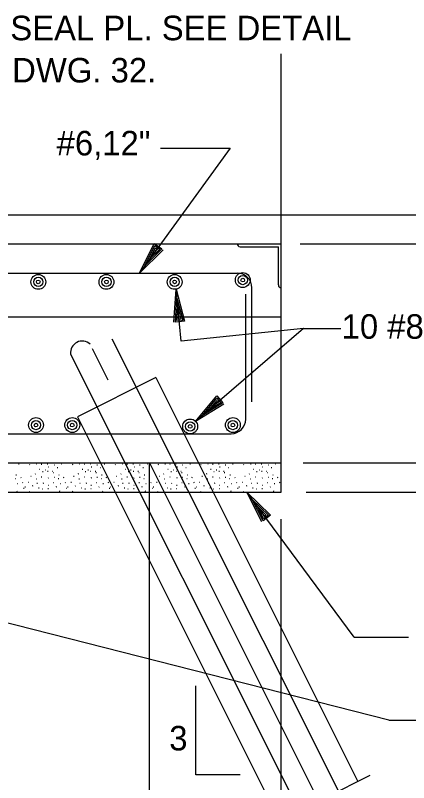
# Model space of a CAD drawing. Extents: x 6 to 106, y 3 to 74.
# Drawn here: x 90.92 to 96.9, y 51.44 to 63.12 of the extents above; entities that cross this region are included whole.
import ezdxf

# ---------------------------------------------------------------- set-up
doc = ezdxf.new("R2010")
doc.units = 0
for name, color, linetype in [('Level 22', 7, 'Continuous'), ('Level 44', 7, 'Continuous'), ('Level 50', 7, 'Continuous')]:
    doc.layers.add(name, color=color, linetype=linetype)

msp = doc.modelspace()

# ---------------------------------------------------------------- linework, layer by layer
at = {"layer": 'Level 22'}
for p, q in [((94.962, 55.863), (94.962, 62.532)), ((94.188, 61.099), (92.808, 59.196)), ((93.129, 61.099), (94.188, 61.099)), ((87.475, 60.085), (98.111, 60.085)), ((89.233, 59.641), (94.962, 59.641)), ((94.337, 59.599), (94.92, 59.599)), ((94.92, 59.016), (94.92, 59.599)), ((95.251, 59.641), (99.7, 59.641)), ((89.722, 59.196), (94.295, 59.196)), ((93.442, 58.16), (93.365, 58.952)), ((94.424, 56.974), (94.424, 58.877)), ((94.517, 57.238), (94.517, 58.974)), ((84.295, 58.53), (94.962, 58.53)), ((95.303, 58.356), (93.442, 58.16)), ((95.303, 58.356), (93.662, 56.94)), ((95.303, 58.356), (95.872, 58.356)), ((92.389, 58.198), (95.832, 51.312)), ((92.091, 58.049), (92.329, 57.572)), ((91.76, 57.965), (95.236, 51.014)), ((93.058, 57.606), (91.865, 57.009)), ((93.058, 57.606), (96.13, 51.461)), ((91.865, 57.009), (94.938, 50.865)), ((84.869, 56.752), (94.202, 56.752)), ((84.295, 56.307), (94.962, 56.307)), ((92.962, 56.307), (96.684, 48.864)), ((92.962, 49.491), (92.962, 56.307)), ((95.297, 56.307), (99.643, 56.307)), ((84.295, 55.863), (94.962, 55.863)), ((96.074, 53.656), (94.439, 55.863)), ((95.342, 55.863), (98.283, 55.863)), ((94.962, 47.814), (94.962, 55.451)), ((96.599, 52.392), (90.406, 53.969)), ((96.074, 53.656), (96.899, 53.656)), ((93.665, 51.56), (93.665, 52.916)), ((96.599, 52.392), (98.151, 52.392)), ((94.337, 51.56), (93.665, 51.56)), ((95.651, 51.221), (96.316, 51.554))]:
    msp.add_line(p, q, dxfattribs=at)
for centre, radius, start, end in [((94.337, 59.641), 0.0417, 180, 270), ((94.295, 58.974), 0.222, 0, 90), ((94.962, 59.016), 0.0417, 180, 270), ((91.937, 57.984), 0.178, 47.1608, 185.9736), ((94.202, 56.974), 0.222, 270, 0)]:
    msp.add_arc(centre, radius, start, end, dxfattribs=at)
at = {"layer": 'Level 44'}
for p, q in [((90.979, 56.29), (90.971, 56.29)), ((91.25, 56.29), (91.243, 56.29)), ((91.629, 56.29), (91.622, 56.29)), ((91.901, 56.29), (91.894, 56.29)), ((92.28, 56.29), (92.273, 56.29)), ((92.552, 56.29), (92.545, 56.29)), ((92.931, 56.29), (92.924, 56.29)), ((93.203, 56.29), (93.195, 56.29)), ((93.582, 56.29), (93.575, 56.29)), ((93.854, 56.29), (93.846, 56.29)), ((94.233, 56.29), (94.225, 56.29)), ((94.504, 56.29), (94.497, 56.29)), ((94.884, 56.29), (94.876, 56.29)), ((91.143, 56.284), (91.135, 56.28)), ((91.294, 56.207), (91.287, 56.206)), ((91.324, 56.285), (91.316, 56.285)), ((91.343, 56.173), (91.334, 56.173)), ((91.38, 56.197), (91.373, 56.197)), ((91.414, 56.288), (91.407, 56.287)), ((91.419, 56.177), (91.412, 56.176)), ((91.431, 56.241), (91.424, 56.241)), ((91.492, 56.177), (91.484, 56.177)), ((91.517, 56.275), (91.51, 56.275)), ((91.566, 56.234), (91.559, 56.233)), ((91.794, 56.284), (91.786, 56.28)), ((91.945, 56.207), (91.938, 56.206)), ((91.975, 56.285), (91.967, 56.285)), ((91.994, 56.173), (91.985, 56.173)), ((92.031, 56.197), (92.024, 56.197)), ((92.065, 56.288), (92.058, 56.287)), ((92.07, 56.177), (92.063, 56.176)), ((92.082, 56.241), (92.075, 56.241)), ((92.143, 56.177), (92.134, 56.177)), ((92.168, 56.275), (92.16, 56.275)), ((92.217, 56.234), (92.209, 56.233)), ((92.445, 56.284), (92.437, 56.28)), ((92.596, 56.207), (92.589, 56.206)), ((92.625, 56.285), (92.618, 56.285)), ((92.644, 56.173), (92.635, 56.173)), ((92.682, 56.197), (92.674, 56.197)), ((92.716, 56.288), (92.709, 56.287)), ((92.721, 56.177), (92.713, 56.176)), ((92.733, 56.241), (92.726, 56.241)), ((92.794, 56.177), (92.785, 56.177)), ((92.819, 56.275), (92.811, 56.275)), ((92.868, 56.234), (92.86, 56.233)), ((93.096, 56.284), (93.088, 56.28)), ((93.247, 56.207), (93.24, 56.206)), ((93.276, 56.285), (93.269, 56.285)), ((93.295, 56.173), (93.286, 56.173)), ((93.333, 56.197), (93.325, 56.197)), ((93.367, 56.288), (93.359, 56.287)), ((93.372, 56.177), (93.364, 56.176)), ((93.384, 56.241), (93.376, 56.241)), ((93.444, 56.177), (93.436, 56.177)), ((93.469, 56.275), (93.462, 56.275)), ((93.518, 56.234), (93.511, 56.233)), ((93.747, 56.284), (93.739, 56.28)), ((93.898, 56.207), (93.89, 56.206)), ((93.927, 56.285), (93.92, 56.285)), ((93.946, 56.173), (93.937, 56.173)), ((93.983, 56.197), (93.976, 56.197)), ((94.018, 56.288), (94.01, 56.287)), ((94.023, 56.177), (94.015, 56.176)), ((94.035, 56.241), (94.027, 56.241)), ((94.095, 56.177), (94.087, 56.177)), ((94.12, 56.275), (94.113, 56.275)), ((94.169, 56.234), (94.162, 56.233)), ((94.397, 56.284), (94.39, 56.28)), ((94.549, 56.207), (94.541, 56.206)), ((94.578, 56.285), (94.571, 56.285)), ((94.597, 56.173), (94.588, 56.173)), ((94.634, 56.197), (94.627, 56.197)), ((94.668, 56.288), (94.661, 56.287)), ((94.673, 56.177), (94.666, 56.176)), ((94.685, 56.241), (94.678, 56.241)), ((94.746, 56.177), (94.738, 56.177)), ((94.771, 56.275), (94.764, 56.275)), ((94.82, 56.234), (94.813, 56.233)), ((90.93, 56.064), (90.922, 56.064)), ((90.937, 56.12), (90.93, 56.12)), ((91.011, 56.083), (91.002, 56.084)), ((91.162, 56.101), (91.155, 56.1)), ((91.228, 56.14), (91.221, 56.139)), ((91.243, 56.062), (91.236, 56.061)), ((91.324, 56.091), (91.316, 56.091)), ((91.427, 56.079), (91.419, 56.078)), ((91.502, 56.157), (91.495, 56.157)), ((91.517, 56.086), (91.51, 56.086)), ((91.581, 56.064), (91.573, 56.064)), ((91.588, 56.12), (91.581, 56.12)), ((91.662, 56.083), (91.653, 56.084)), ((91.813, 56.101), (91.806, 56.1)), ((91.879, 56.14), (91.872, 56.139)), ((91.894, 56.062), (91.886, 56.061)), ((91.975, 56.091), (91.967, 56.091)), ((92.077, 56.079), (92.07, 56.078)), ((92.153, 56.157), (92.146, 56.157)), ((92.168, 56.086), (92.16, 56.086)), ((92.231, 56.064), (92.224, 56.064)), ((92.239, 56.12), (92.231, 56.12)), ((92.313, 56.083), (92.304, 56.084)), ((92.464, 56.101), (92.457, 56.1)), ((92.53, 56.14), (92.523, 56.139)), ((92.545, 56.062), (92.537, 56.061)), ((92.625, 56.091), (92.618, 56.091)), ((92.728, 56.079), (92.721, 56.078)), ((92.804, 56.157), (92.797, 56.157)), ((92.819, 56.086), (92.811, 56.086)), ((92.882, 56.064), (92.875, 56.064)), ((92.89, 56.12), (92.882, 56.12)), ((92.963, 56.083), (92.955, 56.084)), ((93.115, 56.101), (93.107, 56.1)), ((93.181, 56.14), (93.174, 56.139)), ((93.195, 56.062), (93.188, 56.061)), ((93.276, 56.091), (93.269, 56.091)), ((93.379, 56.079), (93.372, 56.078)), ((93.455, 56.157), (93.447, 56.157)), ((93.469, 56.086), (93.462, 56.086)), ((93.533, 56.064), (93.526, 56.064)), ((93.54, 56.12), (93.533, 56.12)), ((93.614, 56.083), (93.606, 56.084)), ((93.766, 56.101), (93.758, 56.1)), ((93.832, 56.14), (93.824, 56.139)), ((93.846, 56.062), (93.839, 56.061)), ((93.927, 56.091), (93.92, 56.091)), ((94.03, 56.079), (94.023, 56.078)), ((94.106, 56.157), (94.098, 56.157)), ((94.12, 56.086), (94.113, 56.086)), ((94.184, 56.064), (94.177, 56.064)), ((94.191, 56.12), (94.184, 56.12)), ((94.265, 56.083), (94.256, 56.084)), ((94.416, 56.101), (94.409, 56.1)), ((94.483, 56.14), (94.475, 56.139)), ((94.497, 56.062), (94.49, 56.061)), ((94.578, 56.091), (94.571, 56.091)), ((94.681, 56.079), (94.673, 56.078)), ((94.756, 56.157), (94.749, 56.157)), ((94.771, 56.086), (94.764, 56.086)), ((94.835, 56.064), (94.827, 56.064)), ((94.842, 56.12), (94.835, 56.12)), ((94.916, 56.083), (94.907, 56.084)), ((90.959, 55.991), (90.952, 55.99)), ((91.035, 56.008), (91.028, 56.007)), ((91.073, 55.937), (91.066, 55.941)), ((91.123, 56.01), (91.116, 56.01)), ((91.187, 55.957), (91.179, 55.956)), ((91.258, 55.996), (91.25, 55.995)), ((91.35, 55.998), (91.341, 55.996)), ((91.427, 55.966), (91.419, 55.966)), ((91.505, 56.007), (91.499, 56.005)), ((91.546, 55.942), (91.539, 55.941)), ((91.61, 55.991), (91.603, 55.99)), ((91.686, 56.008), (91.678, 56.007)), ((91.724, 55.937), (91.716, 55.941)), ((91.774, 56.01), (91.767, 56.01)), ((91.838, 55.957), (91.83, 55.956)), ((91.908, 55.996), (91.901, 55.995)), ((92.001, 55.998), (91.992, 55.996)), ((92.077, 55.966), (92.07, 55.966)), ((92.156, 56.007), (92.15, 56.005)), ((92.197, 55.942), (92.19, 55.941)), ((92.261, 55.991), (92.253, 55.99)), ((92.337, 56.008), (92.329, 56.007)), ((92.375, 55.937), (92.367, 55.941)), ((92.425, 56.01), (92.417, 56.01)), ((92.488, 55.957), (92.481, 55.956)), ((92.559, 55.996), (92.552, 55.995)), ((92.652, 55.998), (92.643, 55.996)), ((92.728, 55.966), (92.721, 55.966)), ((92.807, 56.007), (92.8, 56.005)), ((92.848, 55.942), (92.841, 55.941)), ((92.912, 55.991), (92.904, 55.99)), ((92.987, 56.008), (92.98, 56.007)), ((93.026, 55.937), (93.018, 55.941)), ((93.076, 56.01), (93.068, 56.01)), ((93.139, 55.957), (93.132, 55.956)), ((93.21, 55.996), (93.203, 55.995)), ((93.302, 55.998), (93.293, 55.996)), ((93.379, 55.966), (93.372, 55.966)), ((93.458, 56.007), (93.451, 56.005)), ((93.499, 55.942), (93.492, 55.941)), ((93.562, 55.991), (93.555, 55.99)), ((93.638, 56.008), (93.631, 56.007)), ((93.676, 55.937), (93.669, 55.941)), ((93.726, 56.01), (93.719, 56.01)), ((93.79, 55.957), (93.783, 55.956)), ((93.861, 55.996), (93.854, 55.995)), ((93.953, 55.998), (93.944, 55.996)), ((94.03, 55.966), (94.023, 55.966)), ((94.108, 56.007), (94.102, 56.005)), ((94.15, 55.942), (94.142, 55.941)), ((94.213, 55.991), (94.206, 55.99)), ((94.289, 56.008), (94.282, 56.007)), ((94.327, 55.937), (94.32, 55.941)), ((94.377, 56.01), (94.37, 56.01)), ((94.441, 55.957), (94.433, 55.956)), ((94.512, 55.996), (94.504, 55.995)), ((94.604, 55.998), (94.595, 55.996)), ((94.681, 55.966), (94.673, 55.966)), ((94.759, 56.007), (94.753, 56.005)), ((94.801, 55.942), (94.793, 55.941)), ((94.864, 55.991), (94.857, 55.99)), ((94.94, 56.008), (94.933, 56.007)), ((90.95, 55.875), (90.943, 55.878)), ((91.055, 55.92), (91.047, 55.919)), ((91.143, 55.871), (91.135, 55.87)), ((91.282, 55.922), (91.275, 55.922)), ((91.336, 55.908), (91.329, 55.907)), ((91.424, 55.915), (91.417, 55.914)), ((91.601, 55.875), (91.594, 55.878)), ((91.705, 55.92), (91.698, 55.919)), ((91.794, 55.871), (91.786, 55.87)), ((91.933, 55.922), (91.926, 55.922)), ((91.987, 55.908), (91.979, 55.907)), ((92.075, 55.915), (92.067, 55.914)), ((92.252, 55.875), (92.245, 55.878)), ((92.356, 55.92), (92.349, 55.919)), ((92.444, 55.871), (92.437, 55.87)), ((92.584, 55.922), (92.576, 55.922)), ((92.638, 55.908), (92.63, 55.907)), ((92.726, 55.915), (92.718, 55.914)), ((92.903, 55.875), (92.896, 55.878)), ((93.007, 55.92), (93, 55.919)), ((93.095, 55.871), (93.088, 55.87)), ((93.235, 55.922), (93.227, 55.922)), ((93.288, 55.908), (93.281, 55.907)), ((93.376, 55.915), (93.369, 55.914)), ((93.554, 55.875), (93.547, 55.878)), ((93.658, 55.92), (93.651, 55.919)), ((93.746, 55.871), (93.739, 55.87)), ((93.885, 55.922), (93.878, 55.922)), ((93.939, 55.908), (93.932, 55.907)), ((94.027, 55.915), (94.02, 55.914)), ((94.205, 55.875), (94.198, 55.878)), ((94.309, 55.92), (94.301, 55.919)), ((94.397, 55.871), (94.39, 55.87)), ((94.536, 55.922), (94.529, 55.922)), ((94.59, 55.908), (94.583, 55.907)), ((94.678, 55.915), (94.671, 55.914)), ((94.855, 55.875), (94.848, 55.878)), ((94.96, 55.92), (94.952, 55.919))]:
    msp.add_line(p, q, dxfattribs=at)
at = {"layer": 'Level 50'}
for p, q in [((92.89, 59.309), (92.89, 59.309)), ((92.808, 59.196), (92.808, 59.196)), ((93.365, 58.952), (93.365, 58.952)), ((93.378, 58.814), (93.378, 58.814)), ((93.767, 57.031), (93.767, 57.031)), ((93.662, 56.94), (93.662, 56.94)), ((94.439, 55.863), (94.439, 55.863)), ((94.522, 55.752), (94.522, 55.752))]:
    msp.add_line(p, q, dxfattribs=at)
for points in [[(93.168, 59.551), (92.808, 59.196), (93.034, 59.649), (93.148, 59.566), (92.89, 59.309), (93.043, 59.616), (93.117, 59.562), (92.968, 59.416), (93.052, 59.583), (93.082, 59.561), (93.049, 59.529)], [(93.331, 58.448), (93.365, 58.952), (93.495, 58.464), (93.355, 58.45), (93.378, 58.814), (93.467, 58.483), (93.376, 58.474), (93.391, 58.682), (93.438, 58.501), (93.401, 58.498), (93.405, 58.544)], [(94.093, 57.203), (93.662, 56.94), (93.985, 57.328), (94.077, 57.221), (93.767, 57.031), (93.986, 57.294), (94.046, 57.225), (93.867, 57.118), (93.988, 57.26), (94.012, 57.232), (93.973, 57.208)], [(94.669, 55.413), (94.439, 55.863), (94.802, 55.512), (94.689, 55.427), (94.522, 55.752), (94.768, 55.513), (94.695, 55.459), (94.601, 55.644), (94.734, 55.514), (94.704, 55.492), (94.684, 55.533)]]:
    msp.add_lwpolyline(points, dxfattribs=at)
for centre, radius in [((91.27, 59.063), 0.113), ((91.27, 59.063), 0.0703), ((92.306, 59.063), 0.113), ((92.306, 59.063), 0.0703), ((93.343, 59.063), 0.113), ((93.343, 59.063), 0.0703), ((94.379, 59.091), 0.113), ((94.379, 59.091), 0.0703), ((94.379, 59.091), 0.0281), ((91.27, 59.063), 0.0281), ((92.306, 59.063), 0.0281), ((93.343, 59.063), 0.0281), ((91.235, 56.884), 0.113), ((91.786, 56.884), 0.113), ((94.228, 56.884), 0.113), ((91.235, 56.884), 0.0703), ((91.235, 56.884), 0.0281), ((91.786, 56.884), 0.0703), ((91.786, 56.884), 0.0281), ((93.579, 56.863), 0.113), ((93.579, 56.863), 0.0703), ((93.579, 56.863), 0.0281), ((94.228, 56.884), 0.0703), ((94.228, 56.884), 0.0281)]:
    msp.add_circle(centre, radius, dxfattribs=at)

# ---------------------------------------------------------------- texts
at = {"layer": 'Level 22'}
for s, height, p in [('SEAL PL. SEE DETAIL', 0.37333, (90.844, 62.741)), ('DWG. 32.', 0.3733, (90.872, 62.098)), ('#6,12"', 0.3733, (91.549, 60.988)), ('10 #8', 0.3733, (95.882, 58.198)), ('3', 0.373, (93.261, 51.932))]:
    msp.add_text(s, height=height, dxfattribs=at).set_placement(p)

doc.saveas('drawing.dxf')
